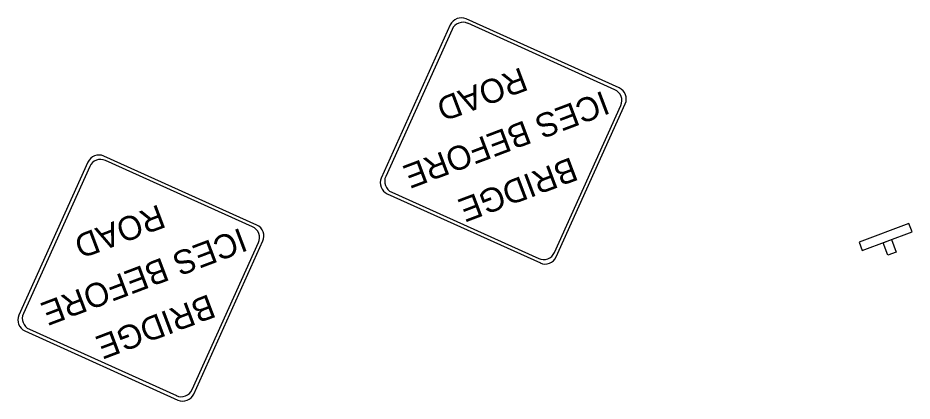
# Model space of a CAD drawing. Extents: x 1581789 to 1622364, y 1043167 to 1103486.
# Drawn here: x 1611456.8 to 1611624.6, y 1092266.2 to 1092338.1 of the extents above; entities that cross this region are included whole.
import ezdxf

# ---------------------------------------------------------------- set-up
doc = ezdxf.new("R2010")
doc.units = 0
doc.layers.add('new 1B', color=7, linetype='Continuous')

msp = doc.modelspace()

# ---------------------------------------------------------------- linework, layer by layer
at = {"layer": 'new 1B'}
for p, q in [((1611537.93, 1092336.74), (1611524.98, 1092308.03)), ((1611569.62, 1092324.92), (1611540.91, 1092337.87)), ((1611568.8, 1092324.6), (1611541.22, 1092337.05)), ((1611538.25, 1092335.92), (1611525.8, 1092308.34)), ((1611557.48, 1092294.05), (1611569.92, 1092321.63)), ((1611557.79, 1092293.23), (1611570.75, 1092321.94)), ((1611501.63, 1092299.2), (1611472.92, 1092312.15)), ((1611500.81, 1092298.89), (1611473.23, 1092311.33)), ((1611469.94, 1092311.03), (1611456.99, 1092282.32)), ((1611470.26, 1092310.21), (1611457.82, 1092282.63)), ((1611526.1, 1092305.05), (1611554.82, 1092292.1)), ((1611526.93, 1092305.37), (1611554.51, 1092292.93)), ((1611489.8, 1092267.51), (1611502.76, 1092296.23)), ((1611489.49, 1092268.34), (1611501.93, 1092295.91)), ((1611458.94, 1092279.66), (1611486.52, 1092267.21)), ((1611458.11, 1092279.34), (1611486.83, 1092266.39))]:
    msp.add_line(p, q, dxfattribs=at)
for points in [[(1611623.98, 1092299.51), (1611614.63, 1092295.97), (1611615.22, 1092294.41), (1611624.57, 1092297.95)], [(1611621.56, 1092294.13), (1611620, 1092293.55), (1611619.12, 1092295.88), (1611620.68, 1092296.47)]]:
    msp.add_lwpolyline(points, close=True, dxfattribs=at)
for centre, start, end in [((1611539.98, 1092335.82), 65.6636, 155.7166), ((1611540.3, 1092334.99), 65.7047, 155.7166), ((1611568.7, 1092322.87), 335.7166, 65.7293), ((1611567.87, 1092322.55), 335.7166, 65.7336), ((1611471.99, 1092310.1), 65.6636, 155.7166), ((1611472.31, 1092309.28), 65.7047, 155.7166), ((1611527.03, 1092307.11), 155.7166, 245.6879), ((1611527.86, 1092307.42), 155.7166, 245.709), ((1611499.88, 1092296.84), 335.7166, 65.7336), ((1611500.71, 1092297.15), 335.7166, 65.7293), ((1611555.43, 1092294.98), 245.7276, 335.7166), ((1611555.74, 1092294.15), 245.7419, 335.7166), ((1611459.04, 1092281.39), 155.7166, 245.6879), ((1611459.87, 1092281.71), 155.7166, 245.709), ((1611487.44, 1092269.27), 245.7276, 335.7166), ((1611487.75, 1092268.44), 245.7419, 335.7166)]:
    msp.add_arc(centre, 2.25, start, end, dxfattribs=at)

# ---------------------------------------------------------------- texts
for s, p in [('ROAD', (1611551.24, 1092328.87)), ('ICES BEFORE', (1611566.59, 1092324.48)), ('BRIDGE', (1611560.64, 1092312.02)), ('ROAD', (1611483.25, 1092303.15)), ('ICES BEFORE', (1611498.61, 1092298.76)), ('BRIDGE', (1611492.65, 1092286.31))]:
    msp.add_text(s, height=4.5, rotation=200.7167, dxfattribs=at).set_placement(p)

doc.saveas('drawing.dxf')
